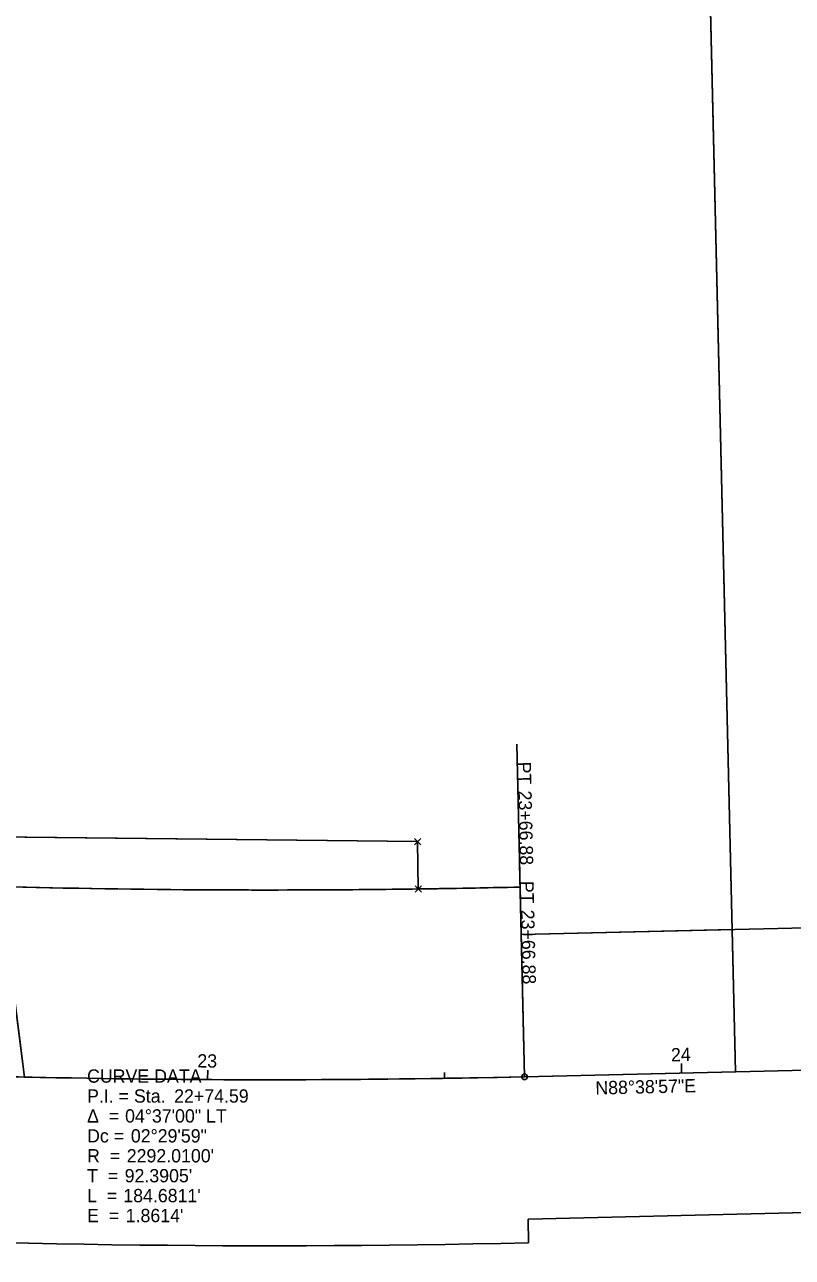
# Model space of a CAD drawing. Extents: x 2273111 to 2279616, y 652916 to 655718.
# Drawn here: x 2274766.6 to 2274928.6, y 654659.4 to 654919.2 of the extents above; entities that cross this region are included whole.
import ezdxf

# ---------------------------------------------------------------- set-up
doc = ezdxf.new("R2010")
doc.units = 0
for name, color, linetype in [('DV_X_Property_Line', 7, 'Continuous'), ('RW_P_Easement_Area', 7, 'Continuous'), ('RW_P_Esmt_TMP', 7, 'Continuous'), ('RW_X_CL', 7, 'Continuous'), ('RW_X_CL_1000_Curve_Data', 7, 'Continuous'), ('RW_X_CL_1000_Stations', 7, 'Continuous'), ('RW_X_CL_100_Curve_Data', 7, 'Continuous'), ('RW_X_CL_100_Stations', 7, 'Continuous'), ('RW_X_CL_500_Curve_Data', 7, 'Continuous'), ('RW_X_CL_500_Stations', 7, 'Continuous'), ('RW_X_Esmt_SH', 7, 'Continuous'), ('SC_Scratch3', 7, 'Continuous'), ('SC_Scratch4', 7, 'Continuous'), ('SC_Scratch5', 7, 'Continuous')]:
    doc.layers.add(name, color=color, linetype=linetype)

msp = doc.modelspace()

# ---------------------------------------------------------------- linework, layer by layer
at = {"layer": 'DV_X_Property_Line'}
for p, q in [((2274905.28, 655179.09), (2274916.62, 654698.48)), ((2274766.64, 654697.37), (2274705.29, 655177.83))]:
    msp.add_line(p, q, dxfattribs=at)
at = {"layer": 'RW_P_Easement_Area'}
for p, q in [((2274760.17, 654748.01), (2274849.53, 654747.02)), ((2274848.87, 654746.35), (2274850.2, 654747.69)), ((2274848.87, 654747.69), (2274850.2, 654746.35)), ((2274849.53, 654747.02), (2274849.67, 654737.02)), ((2274849.01, 654736.35), (2274850.34, 654737.69)), ((2274849.01, 654737.69), (2274850.34, 654736.35))]:
    msp.add_line(p, q, dxfattribs=at)
msp.add_arc((2274818.07, 656988.81), 2252.01, 268.56091, 270.80398, dxfattribs=at)
at = {"layer": 'RW_P_Esmt_TMP'}
for p, q in [((2274737.06, 654748.26), (2274849.53, 654747.02)), ((2274737.06, 654748.26), (2274849.53, 654747.02)), ((2274849.53, 654747.02), (2274849.67, 654737.02)), ((2274849.53, 654747.02), (2274849.67, 654737.02))]:
    msp.add_line(p, q, dxfattribs=at)
at = {"layer": 'RW_X_CL'}
msp.add_line((2274872.11, 654697.43), (2275371.97, 654709.22), dxfattribs=at)
msp.add_arc((2274818.07, 656988.81), 2292.01, 266.73428, 271.35095, dxfattribs=at)
at = {"layer": 'RW_X_CL_1000_Stations'}
msp.add_line((2274872.11, 654697.43), (2274871.05, 654742.42), dxfattribs=at)
msp.add_circle((2274872.11, 654697.43), 0.6, dxfattribs=at)
at = {"layer": 'RW_X_CL_100_Stations'}
for p, q in [((2274872.11, 654697.43), (2274870.49, 654767.55)), ((2274905.22, 654698.22), (2274905.17, 654700.21)), ((2274805.23, 654696.83), (2274805.25, 654698.83)), ((2274855.23, 654697.1), (2274855.21, 654698.3))]:
    msp.add_line(p, q, dxfattribs=at)
msp.add_circle((2274872.11, 654697.43), 0.6, dxfattribs=at)
at = {"layer": 'RW_X_CL_500_Stations'}
for p, q in [((2274872.11, 654697.43), (2274871.05, 654742.42)), ((2274905.22, 654698.22), (2274905.19, 654699.42))]:
    msp.add_line(p, q, dxfattribs=at)
msp.add_circle((2274872.11, 654697.43), 0.6, dxfattribs=at)
at = {"layer": 'RW_X_Esmt_SH'}
for p, q in [((2274871.4, 654727.43), (2275371.26, 654739.21)), ((2274871.17, 654737.42), (2274871.4, 654727.43)), ((2274872.82, 654667.44), (2275372.68, 654679.23)), ((2274872.94, 654662.44), (2274872.82, 654667.44))]:
    msp.add_line(p, q, dxfattribs=at)
for radius in [2252.01, 2327.01]:
    msp.add_arc((2274818.07, 656988.81), radius, 266.73428, 271.35095, dxfattribs=at)
at = {"layer": 'SC_Scratch3'}
msp.add_lwpolyline([(2274761.52, 654737.51), (2274760.18, 654748.01), (2274849.53, 654747.02), (2274849.67, 654737.02)], dxfattribs=at)
msp.add_arc((2274818.07, 656988.81), 2252.01, 268.56095, 270.80398, dxfattribs=at)
at = {"layer": 'SC_Scratch4'}
for p, q in [((2274761.52, 654737.51), (2274766.64, 654697.37)), ((2274766.64, 654697.37), (2274761.52, 654737.51))]:
    msp.add_line(p, q, dxfattribs=at)
for points in [[(2274872.94, 654662.44), (2274872.82, 654667.44), (2275372.68, 654679.23), (2277600.46, 654731.77), (2277807.61, 654774.72), (2278555.98, 655078.21), (2277480.44, 654017.71), (2277501.49, 653996.33), (2278684.33, 655162.63), (2277798.86, 654803.54), (2277597.03, 654761.7), (2275371.97, 654709.22), (2274872.11, 654697.43)], [(2274871.17, 654737.42), (2274871.4, 654727.43), (2274915.91, 654728.48), (2274916.62, 654698.48), (2274872.11, 654697.43)]]:
    msp.add_lwpolyline(points, dxfattribs=at)
for radius, start, end in [(2252.01, 268.56095, 270.80398), (2252.01, 270.80398, 271.35095), (2292.01, 266.73428, 271.35095), (2292.01, 266.73428, 268.71423), (2292.01, 268.71423, 271.35095), (2327.01, 266.73428, 271.35095)]:
    msp.add_arc((2274818.07, 656988.81), radius, start, end, dxfattribs=at)
at = {"layer": 'SC_Scratch5'}
for points in [[(2274766.64, 654697.37), (2274705.29, 655177.83), (2274905.28, 655179.09), (2274916.62, 654698.48), (2274872.11, 654697.43)], [(2274687.5, 654700.52), (2274458.12, 654713.61), (2274339.92, 654913.73), (2274394.14, 654990.65), (2274486.83, 655028.17), (2274732.19, 654967.18), (2274766.64, 654697.37)]]:
    msp.add_lwpolyline(points, dxfattribs=at)
for start, end in [(266.73428, 268.71423), (268.71423, 271.35095)]:
    msp.add_arc((2274818.07, 656988.81), 2292.01, start, end, dxfattribs=at)

# ---------------------------------------------------------------- texts
at = {"layer": 'RW_X_CL_1000_Curve_Data'}
for s, p in [('CURVE DATA', (2274779.81, 654696.18)), ('P.I. = Sta. ', (2274779.81, 654691.98)), ('22+74.59', (2274798.18, 654691.98)), ('Δ  = ', (2274779.81, 654687.78)), ('04°37\'00" LT', (2274787.83, 654687.78)), ('Dc = ', (2274779.81, 654683.58)), ('02°29\'59"', (2274789.05, 654683.58)), ('R  = ', (2274779.81, 654679.38)), ("2292.0100'", (2274788.18, 654679.38)), ('T  = ', (2274779.81, 654675.18)), ("92.3905'", (2274787.74, 654675.18)), ('L  = ', (2274779.81, 654670.98)), ("184.6811'", (2274787.45, 654670.98)), ('E  = ', (2274779.81, 654666.78)), ("1.8614'", (2274787.96, 654666.78))]:
    msp.add_text(s, height=2.8, dxfattribs=at).set_placement(p)
at = {"layer": 'RW_X_CL_1000_Stations'}
for s, p in [('PT', (2274871.18, 654738.69)), ('23+66.88', (2274871.33, 654732.61))]:
    msp.add_text(s, height=2.8, rotation=271.351, dxfattribs=at).set_placement(p)
at = {"layer": 'RW_X_CL_100_Curve_Data'}
msp.add_text('N88°38\'57"E', height=2.8, rotation=1.351, dxfattribs=at).set_placement((2274887.06, 654693.67))
at = {"layer": 'RW_X_CL_100_Stations'}
for s, rotation, p in [('PT', 271.351, (2274870.62, 654763.82)), ('23+66.88', 271.351, (2274870.77, 654757.73)), ('24', 1.351, (2274903.01, 654700.66)), ('23', 359.6791, (2274803.07, 654699.39))]:
    msp.add_text(s, height=2.8, rotation=rotation, dxfattribs=at).set_placement(p)
at = {"layer": 'RW_X_CL_500_Curve_Data'}
for s, p in [('CURVE DATA', (2274779.81, 654696.18)), ('P.I. = Sta. ', (2274779.81, 654691.98)), ('22+74.59', (2274798.18, 654691.98)), ('Δ  = ', (2274779.81, 654687.78)), ('04°37\'00" LT', (2274787.83, 654687.78)), ('Dc = ', (2274779.81, 654683.58)), ('02°29\'59"', (2274789.05, 654683.58)), ('R  = ', (2274779.81, 654679.38)), ("2292.0100'", (2274788.18, 654679.38)), ('T  = ', (2274779.81, 654675.18)), ("92.3905'", (2274787.74, 654675.18)), ('L  = ', (2274779.81, 654670.98)), ("184.6811'", (2274787.45, 654670.98)), ('E  = ', (2274779.81, 654666.78)), ("1.8614'", (2274787.96, 654666.78))]:
    msp.add_text(s, height=2.8, dxfattribs=at).set_placement(p)
at = {"layer": 'RW_X_CL_500_Stations'}
for s, p in [('PT', (2274871.18, 654738.69)), ('23+66.88', (2274871.33, 654732.61))]:
    msp.add_text(s, height=2.8, rotation=271.351, dxfattribs=at).set_placement(p)

doc.saveas('drawing.dxf')
